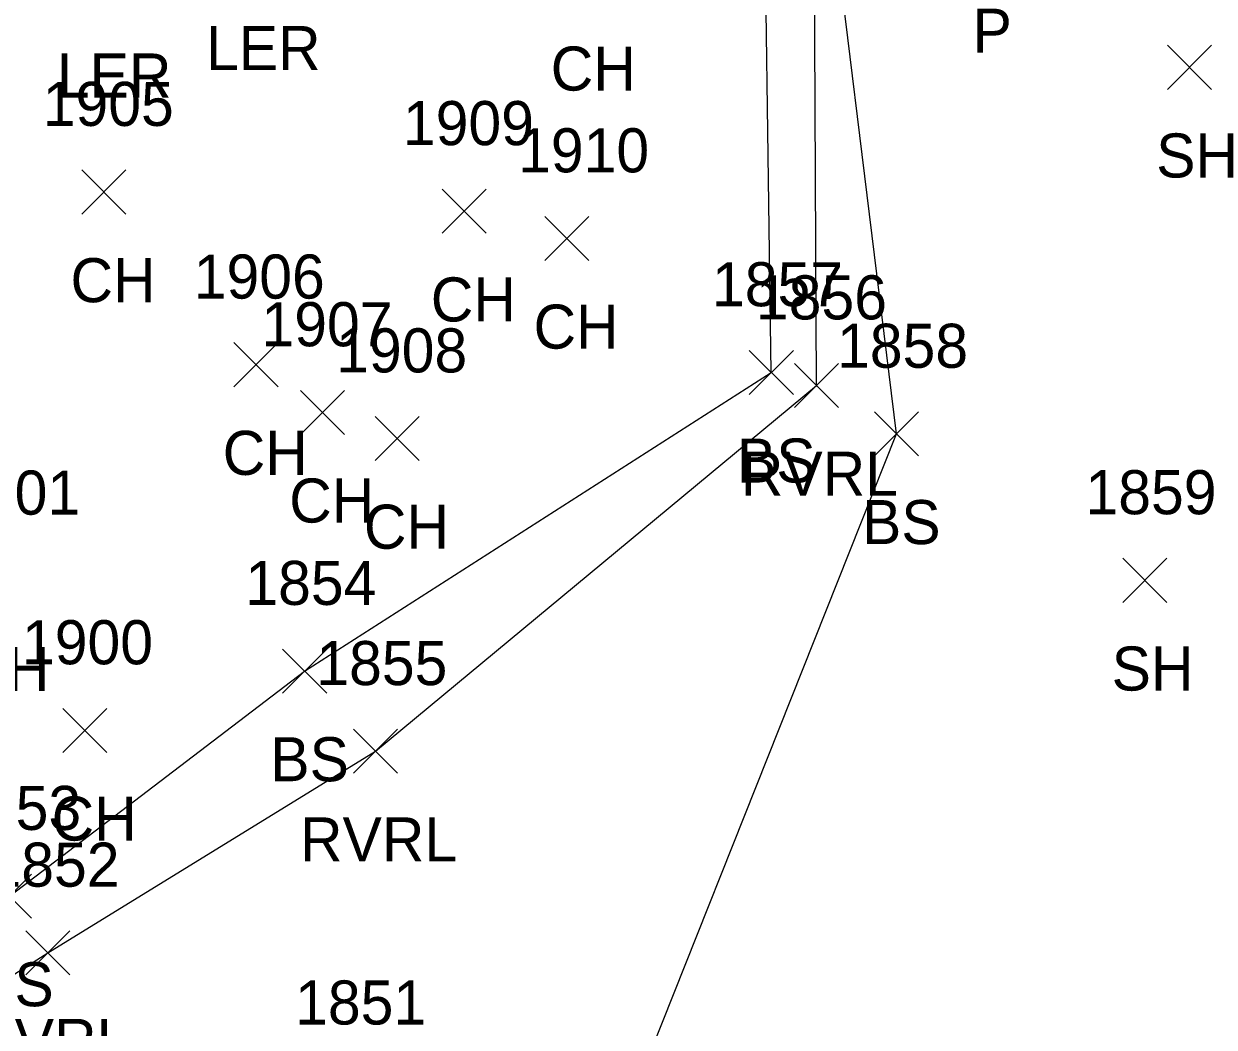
# Model space of a CAD drawing. Extents: x 1638344 to 1639591, y 610835 to 612202.
# Drawn here: x 1638686.8 to 1638740.9, y 611608.8 to 611654.3 of the extents above; entities that cross this region are included whole.
import ezdxf

# ---------------------------------------------------------------- set-up
doc = ezdxf.new("R2010")
doc.units = 0
for name, color, linetype in [('D_A', 7, 'Continuous'), ('L_A', 7, 'Continuous'), ('L_I', 7, 'Continuous'), ('L_TIC', 7, 'Continuous'), ('LAWE', 7, 'Continuous'), ('LELB', 7, 'Continuous')]:
    doc.layers.add(name, color=color, linetype=linetype)

msp = doc.modelspace()

# ---------------------------------------------------------------- linework, layer by layer
at = {"layer": 'L_TIC'}
for points in [[(1638738.763, 611651.336), (1638740.763, 611653.336)], [(1638740.763, 611651.336), (1638738.763, 611653.336)], [(1638689.475, 611645.677), (1638691.475, 611647.677)], [(1638691.475, 611645.677), (1638689.475, 611647.677)], [(1638705.832, 611644.804), (1638707.832, 611646.804)], [(1638707.832, 611644.804), (1638705.832, 611646.804)], [(1638710.495, 611643.571), (1638712.495, 611645.571)], [(1638712.495, 611643.571), (1638710.495, 611645.571)], [(1638696.385, 611637.843), (1638698.385, 611639.843)], [(1638698.385, 611637.843), (1638696.385, 611639.843)], [(1638719.779, 611637.494), (1638721.779, 611639.494)], [(1638721.779, 611637.494), (1638719.779, 611639.494)], [(1638721.828, 611636.898), (1638723.828, 611638.898)], [(1638723.828, 611636.898), (1638721.828, 611638.898)], [(1638699.404, 611635.68), (1638701.404, 611637.68)], [(1638701.404, 611635.68), (1638699.404, 611637.68)], [(1638702.796, 611634.493), (1638704.796, 611636.493)], [(1638704.796, 611634.493), (1638702.796, 611636.493)], [(1638725.456, 611634.702), (1638727.456, 611636.702)], [(1638727.456, 611634.702), (1638725.456, 611636.702)], [(1638736.741, 611628.058), (1638738.741, 611630.058)], [(1638738.741, 611628.058), (1638736.741, 611630.058)], [(1638698.594, 611623.943), (1638700.594, 611625.943)], [(1638700.594, 611623.943), (1638698.594, 611625.943)], [(1638688.618, 611621.251), (1638690.618, 611623.251)], [(1638690.618, 611621.251), (1638688.618, 611623.251)], [(1638701.816, 611620.305), (1638703.816, 611622.305)], [(1638703.816, 611620.305), (1638701.816, 611622.305)], [(1638685.193, 611613.735), (1638687.193, 611615.735)], [(1638687.193, 611613.735), (1638685.193, 611615.735)], [(1638686.934, 611611.159), (1638688.934, 611613.159)], [(1638688.934, 611611.159), (1638686.934, 611613.159)]]:
    msp.add_lwpolyline(points, dxfattribs=at)
at = {"layer": 'LAWE'}
msp.add_lwpolyline([(1638671.011, 611601.41), (1638687.934, 611612.159), (1638702.816, 611621.305), (1638722.828, 611637.898), (1638722.694, 611666.366), (1638723.119, 611679.868), (1638719.094, 611692.553), (1638717.187, 611697.341), (1638711.048, 611700.649), (1638718.685, 611716.114), (1638719.359, 611723.061), (1638714.323, 611734.571), (1638714.704, 611747.214), (1638712.56, 611755.84), (1638714.994, 611761.22), (1638711.865, 611767.72), (1638710.522, 611777.786), (1638714.936, 611789.326), (1638716.942, 611806.826), (1638715.698, 611824.36)], dxfattribs=at)
at = {"layer": 'LELB'}
for points in [[(1638680.248, 611562.888), (1638697.03, 611576.026), (1638709.984, 611594.301), (1638726.456, 611635.702), (1638722.694, 611666.366)], [(1638669.405, 611602.331), (1638686.193, 611614.735), (1638699.594, 611624.943), (1638720.779, 611638.494), (1638720.387, 611665.845)]]:
    msp.add_lwpolyline(points, dxfattribs=at)

# ---------------------------------------------------------------- texts
at = {"layer": 'D_A'}
msp.add_text('P', height=2, dxfattribs=at).set_placement((1638729.916, 611652.996))
at = {"layer": 'L_A'}
for s, p in [('LER', (1638695.117, 611652.21)), ('CH', (1638710.764, 611651.28)), ('LER', (1638688.345, 611650.965)), ('SH', (1638738.251, 611647.336)), ('CH', (1638688.963, 611641.677)), ('CH', (1638705.32, 611640.804)), ('CH', (1638709.984, 611639.571)), ('CH', (1638695.873, 611633.843)), ('BS', (1638719.22, 611633.494)), ('RVRL', (1638719.395, 611632.898)), ('CH', (1638698.892, 611631.68)), ('BS', (1638724.897, 611630.702)), ('CH', (1638702.284, 611630.493)), ('CH', (1638684.145, 611624.041)), ('SH', (1638736.229, 611624.058)), ('BS', (1638698.035, 611619.943)), ('CH', (1638688.107, 611617.251)), ('RVRL', (1638699.383, 611616.305)), ('BS', (1638684.634, 611609.735)), ('RVRL', (1638684.501, 611607.159))]:
    msp.add_text(s, height=2, dxfattribs=at).set_placement(p)
at = {"layer": 'L_I'}
for s, p in [('1905', (1638687.703, 611649.677)), ('1909', (1638704.053, 611648.804)), ('1910', (1638709.283, 611647.571)), ('1906', (1638694.558, 611641.843)), ('1857', (1638718.086, 611641.494)), ('1856', (1638720.08, 611640.898)), ('1907', (1638697.633, 611639.68)), ('1908', (1638701.024, 611638.493)), ('1858', (1638723.763, 611638.702)), ('1901', (1638683.452, 611632.041)), ('1859', (1638735.04, 611632.058)), ('1854', (1638696.901, 611627.943)), ('1900', (1638686.76, 611625.251)), ('1855', (1638700.123, 611624.305)), ('1853', (1638683.5, 611617.735)), ('1852', (1638685.241, 611615.159)), ('1851', (1638699.161, 611608.905))]:
    msp.add_text(s, height=2, dxfattribs=at).set_placement(p)

doc.saveas('drawing.dxf')
